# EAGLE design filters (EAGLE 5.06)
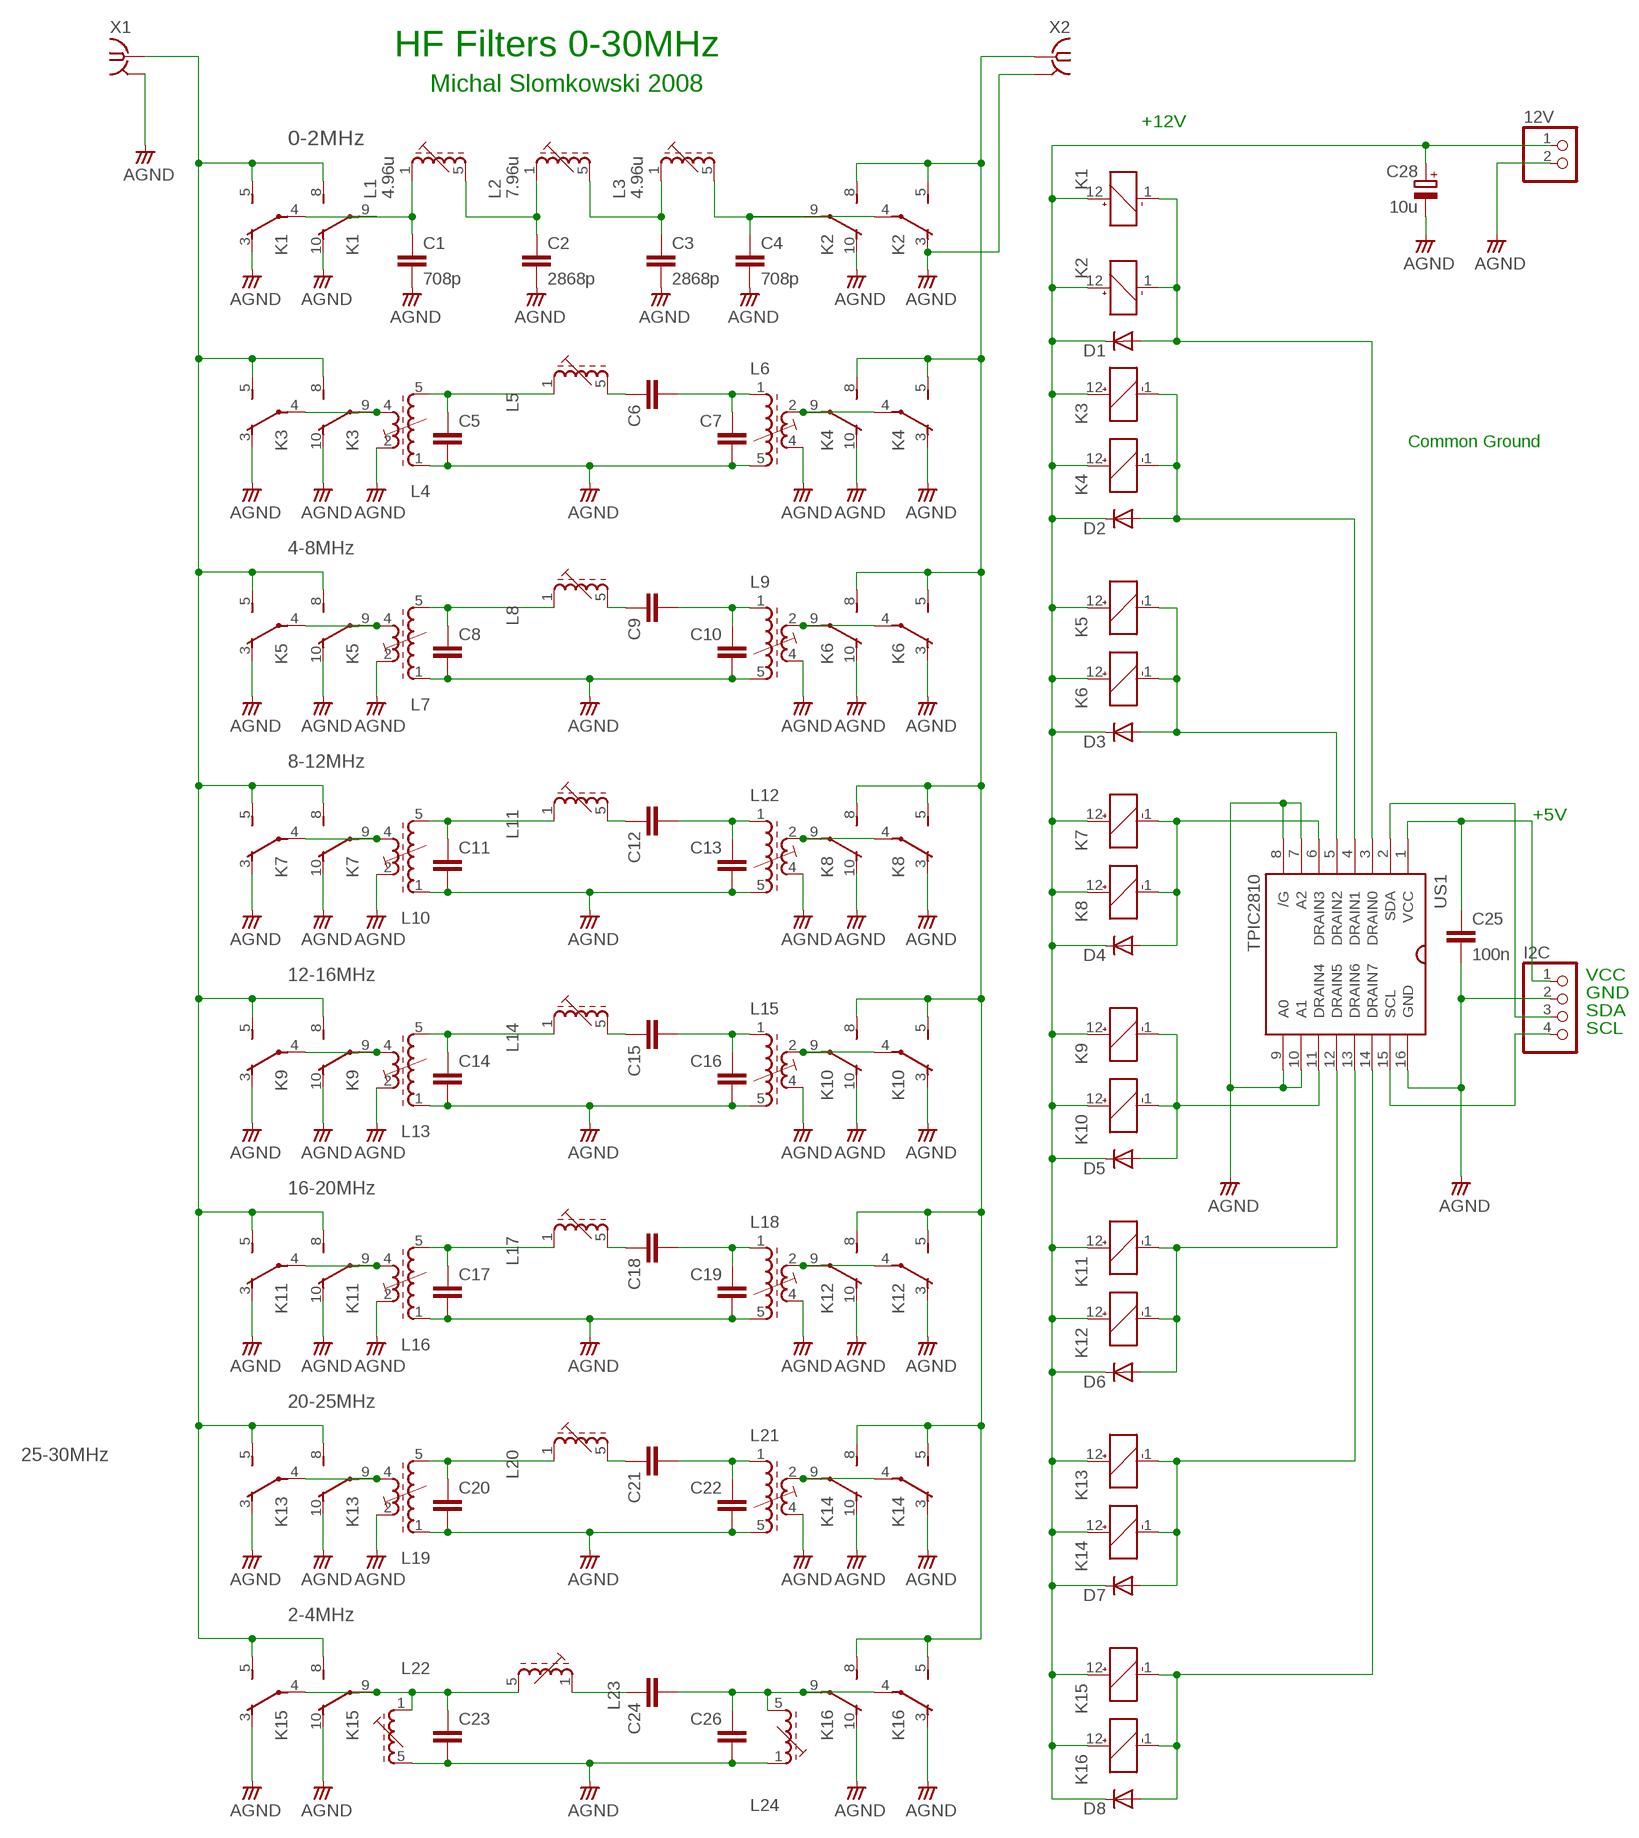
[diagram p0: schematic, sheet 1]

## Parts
12V  PINHD-1X2  [1X02]
C1  708p  C-EU025_050-025X075  [C025_050-025X075]
C2  2868p  C-EU025_050-025X075  [C025_050-025X075]
C3  2868p  C-EU025_050-025X075  [C025_050-025X075]
C4  708p  C-EU025_050-025X075  [C025_050-025X075]
C5  C-EU025_050-025X075  [C025_050-025X075]
C6  C-EU025_050-025X075  [C025_050-025X075]
C7  C-EU025_050-025X075  [C025_050-025X075]
C8  C-EU025_050-025X075  [C025_050-025X075]
C9  C-EU025_050-025X075  [C025_050-025X075]
C10  C-EU025_050-025X075  [C025_050-025X075]
C11  C-EU025_050-025X075  [C025_050-025X075]
C12  C-EU025_050-025X075  [C025_050-025X075]
C13  C-EU025_050-025X075  [C025_050-025X075]
C14  C-EU025_050-025X075  [C025_050-025X075]
C15  C-EU025_050-025X075  [C025_050-025X075]
C16  C-EU025_050-025X075  [C025_050-025X075]
C17  C-EU025_050-025X075  [C025_050-025X075]
C18  C-EU025_050-025X075  [C025_050-025X075]
C19  C-EU025_050-025X075  [C025_050-025X075]
C20  C-EU025_050-025X075  [C025_050-025X075]
C21  C-EU025_050-025X075  [C025_050-025X075]
C22  C-EU025_050-025X075  [C025_050-025X075]
C23  C-EU025_050-025X075  [C025_050-025X075]
C24  C-EU025_050-025X075  [C025_050-025X075]
C25  100n  C-EUC0805K  [C0805K]
C26  C-EU025_050-025X075  [C025_050-025X075]
C28  10u  CPOL-EUE2.5-7  [E2,5-7]
D1  PMLL4150  [SOD80C]
D2  PMLL4150  [SOD80C]
D3  PMLL4150  [SOD80C]
D4  PMLL4150  [SOD80C]
D5  PMLL4150  [SOD80C]
D6  PMLL4150  [SOD80C]
D7  PMLL4150  [SOD80C]
D8  PMLL4150  [SOD80C]
I2C  PINHD-1X4  [1X04]
K1  TX2SO-L-12V  [TX2]
K2  TX2SO-L-12V  [TX2]
K3  TX2SO-L-12V  [TX2]
K4  TX2SO-L-12V  [TX2]
K5  TX2SO-L-12V  [TX2]
K6  TX2SO-L-12V  [TX2]
K7  TX2SO-L-12V  [TX2]
K8  TX2SO-L-12V  [TX2]
K9  TX2SO-L-12V  [TX2]
K10  TX2SO-L-12V  [TX2]
K11  TX2SO-L-12V  [TX2]
K12  TX2SO-L-12V  [TX2]
K13  TX2SO-L-12V  [TX2]
K14  TX2SO-L-12V  [TX2]
K15  TX2SO-L-12V  [TX2]
K16  TX2SO-L-12V  [TX2]
L1  4.96u  51K  [71K]
L2  7.96u  51K  [71K]
L3  4.96u  51K  [71K]
L4  71-4-1524  [71-5]
L5  51K  [71K]
L6  71-4-1524  [71-5]
L7  71-4-1524  [71-5]
L8  51K  [71K]
L9  71-4-1524  [71-5]
L10  71-4-1524  [71-5]
L11  51K  [71K]
L12  71-4-1524  [71-5]
L13  71-4-1524  [71-5]
L14  51K  [71K]
L15  71-4-1524  [71-5]
L16  71-4-1524  [71-5]
L17  51K  [71K]
L18  71-4-1524  [71-5]
L19  71-4-1524  [71-5]
L20  51K  [71K]
L21  71-4-1524  [71-5]
L22  51K  [71K]
L23  51K  [71K]
L24  51K  [71K]
US1  TPIC2810  [SO16]
X1  BU-SMA-V  [BU-SMA-V]
X2  BU-SMA-V  [BU-SMA-V]

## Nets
N$1: C1.1 K1.4(1:P) K1.9(2:P) L1.1(A)
N$2: C2.1 L1.5(E) L2.1(A)
N$3: C3.1 L2.5(E) L3.1(A)
N$4: C5.1 L4.5(E1) L5.1(A)
N$5: K2.5(1:S) K2.8(2:S) K4.5(1:S) K4.8(2:S) K6.5(1:S) K6.8(2:S) K8.5(1:S) K8.8(2:S) K10.5(1:S) K10.8(2:S) K12.5(1:S) K12.8(2:S) K14.5(1:S) K14.8(2:S) K16.5(1:S) K16.8(2:S) X2.1
N$6: K6.4(1:P) K6.9(2:P) L9.2(A2)
N$8: C4.1 K2.4(1:P) K2.9(2:P) L3.5(E)
N$9: D7.A K13.1(_:-) K14.1(_:-) US1.13(DRAIN6)
N$10: K5.4(1:P) K5.9(2:P) L7.4(E2)
N$11: K12.4(1:P) K12.9(2:P) L18.2(A2)
N$12: K4.4(1:P) K4.9(2:P) L6.2(A2)
N$13: C6.2 C7.1 L6.1(A1)
N$14: C6.1 L5.5(E)
N$15: I2C.3 US1.2(SDA)
N$17: K3.4(1:P) K3.9(2:P) L4.4(E2)
N$18: K7.4(1:P) K7.9(2:P) L10.4(E2)
N$19: K13.4(1:P) K13.9(2:P) L19.4(E2)
N$20: C23.1 K15.4(1:P) K15.9(2:P) L22.1(A) L23.5(E)
N$21: C24.1 L23.1(A)
N$22: C24.2 C26.1 K16.4(1:P) K16.9(2:P) L24.5(E)
N$25: K8.4(1:P) K8.9(2:P) L12.2(A2)
N$26: K9.4(1:P) K9.9(2:P) L13.4(E2)
N$27: K1.5(1:S) K1.8(2:S) K3.5(1:S) K3.8(2:S) K5.5(1:S) K5.8(2:S) K7.5(1:S) K7.8(2:S) K9.5(1:S) K9.8(2:S) K11.5(1:S) K11.8(2:S) K13.5(1:S) K13.8(2:S) K15.5(1:S) K15.8(2:S) X1.1
N$28: K10.4(1:P) K10.9(2:P) L15.2(A2)
N$29: C21.2 C22.1 L21.1(A1)
N$30: C21.1 L20.5(E)
N$31: K11.4(1:P) K11.9(2:P) L16.4(E2)
N$32: C20.1 L19.5(E1) L20.1(A)
N$33: C18.2 C19.1 L18.1(A1)
N$34: K14.4(1:P) K14.9(2:P) L21.2(A2)
N$35: C18.1 L17.5(E)
N$36: C17.1 L16.5(E1) L17.1(A)
N$38: C15.2 C16.1 L15.1(A1)
N$39: C15.1 L14.5(E)
N$41: C14.1 L13.5(E1) L14.1(A)
N$42: C12.2 C13.1 L12.1(A1)
N$43: C12.1 L11.5(E)
N$46: D4.A K7.1(_:-) K8.1(_:-) US1.6(DRAIN3)
N$47: D5.A K9.1(_:-) K10.1(_:-) US1.11(DRAIN4)
N$49: C11.1 L10.5(E1) L11.1(A)
N$50: C9.2 C10.1 L9.1(A1)
N$51: C9.1 L8.5(E)
N$52: C8.1 L7.5(E1) L8.1(A)
N$53: D1.A K1.1(_:-) K2.1(_:-) US1.3(DRAIN0)
N$54: D2.A K3.1(_:-) K4.1(_:-) US1.4(DRAIN1)
N$142: D8.A K15.1(_:-) K16.1(_:-) US1.14(DRAIN7)
N$143: D6.A K11.1(_:-) K12.1(_:-) US1.12(DRAIN5)
N$144: D3.A K5.1(_:-) K6.1(_:-) US1.5(DRAIN2)
N$156: C25.1 I2C.1 US1.1(VCC)
N$189: I2C.4 US1.15(SCL)
N$191: 12V.2 C1.2 C2.2 C3.2 C4.2 C5.2 C7.2 C8.2 C10.2 C11.2 C13.2 C14.2 C16.2 C17.2 C19.2 C20.2 C22.2 C23.2 C25.2 C26.2 C28.- I2C.2 K1.3(1:O) K1.10(2:O) K2.3(1:O) K2.10(2:O) K3.3(1:O) K3.10(2:O) K4.3(1:O) K4.10(2:O) K5.3(1:O) K5.10(2:O) K6.3(1:O) K6.10(2:O) K7.3(1:O) K7.10(2:O) K8.3(1:O) K8.10(2:O) K9.3(1:O) K9.10(2:O) K10.3(1:O) K10.10(2:O) K11.3(1:O) K11.10(2:O) K12.3(1:O) K12.10(2:O) K13.3(1:O) K13.10(2:O) K14.3(1:O) K14.10(2:O) K15.3(1:O) K15.10(2:O) K16.3(1:O) K16.10(2:O) L4.1(A1) L4.2(A2) L6.4(E2) L6.5(E1) L7.1(A1) L7.2(A2) L9.4(E2) L9.5(E1) L10.1(A1) L10.2(A2) L12.4(E2) L12.5(E1) L13.1(A1) L13.2(A2) L15.4(E2) L15.5(E1) L16.1(A1) L16.2(A2) L18.4(E2) L18.5(E1) L19.1(A1) L19.2(A2) L21.4(E2) L21.5(E1) L22.5(E) L24.1(A) US1.7(A2) US1.8(/G) US1.9(A0) US1.10(A1) US1.16(GND) X1.2(GND) X2.2(GND) ; supply symbol labelled AGND
N$195: 12V.1 C28.+ D1.C D2.C D3.C D4.C D5.C D6.C D7.C D8.C K1.12(_:+) K2.12(_:+) K3.12(_:+) K4.12(_:+) K5.12(_:+) K6.12(_:+) K7.12(_:+) K8.12(_:+) K9.12(_:+) K10.12(_:+) K11.12(_:+) K12.12(_:+) K13.12(_:+) K14.12(_:+) K15.12(_:+) K16.12(_:+)
Unconnected: L1.S1(S2) L1.S2(S1) L2.S1(S2) L2.S2(S1) L3.S1(S2) L3.S2(S1) L4.S1 L4.S2 L5.S1(S2) L5.S2(S1) L6.S1 L6.S2 L7.S1 L7.S2 L8.S1(S2) L8.S2(S1) L9.S1 L9.S2 L10.S1 L10.S2 L11.S1(S2) L11.S2(S1) L12.S1 L12.S2 L13.S1 L13.S2 L14.S1(S2) L14.S2(S1) L15.S1 L15.S2 L16.S1 L16.S2 L17.S1(S2) L17.S2(S1) L18.S1 L18.S2 L19.S1 L19.S2 L20.S1(S2) L20.S2(S1) L21.S1 L21.S2 L22.S1(S2) L22.S2(S1) L23.S1(S2) L23.S2(S1) L24.S1(S2) L24.S2(S1)

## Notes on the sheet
- HF Filters 0-30MHz
- Michal Slomkowski 2008
- +12V
- 0-2MHz
- Common Ground
- 4-8MHz
- 8-12MHz
- +5V
- 12-16MHz | VCC
- GND
- SDA
- SCL
- 16-20MHz
- 20-25MHz
- 25-30MHz
- 2-4MHz

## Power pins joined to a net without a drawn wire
GND: X1.3(GND) X1.4(GND) X1.5(GND) X2.3(GND) X2.4(GND) X2.5(GND)

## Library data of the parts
12V = pinhead:PINHD-1X2: PIN HEADER
C1-C26 = rcl:C-EU: CAPACITOR, European symbol
C28 = rcl:CPOL-EU: POLARIZED CAPACITOR, European symbol
D1-D8 = diode:PMLL4150: DIODE
I2C = pinhead:PINHD-1X4: PIN HEADER
K1-K16 = relay:TX2SO?-*: 2 AMP. HIGH CAPACITY RELAY NAiS WITH HIGH SURGE VOLTAGE & HIGH BREAKDOWN VOLTAGE Source: http://www.mew-europe.com/.. en_ds_61022_0001.pdf
L1-L3 L5 L8 L11 L14 L17 L20 L22-L24 = inductor-neosid:51K: FILTER pre-adjusted RF filter, type K, standard value E-12
L4 L6 L7 L9 L10 L12 L13 L15 L16 L18 L19 L21 = inductor-neosid:71-4-: TRANSFORMER adjustable filter transformer
US1 = receiver:TPIC2810: 8-Bit LED Driver with I2C Interface
X1 X2 = con-coax:BU-SMA-V: FEMALE SMA CONNECTOR Radiall distributor RS 112-3794

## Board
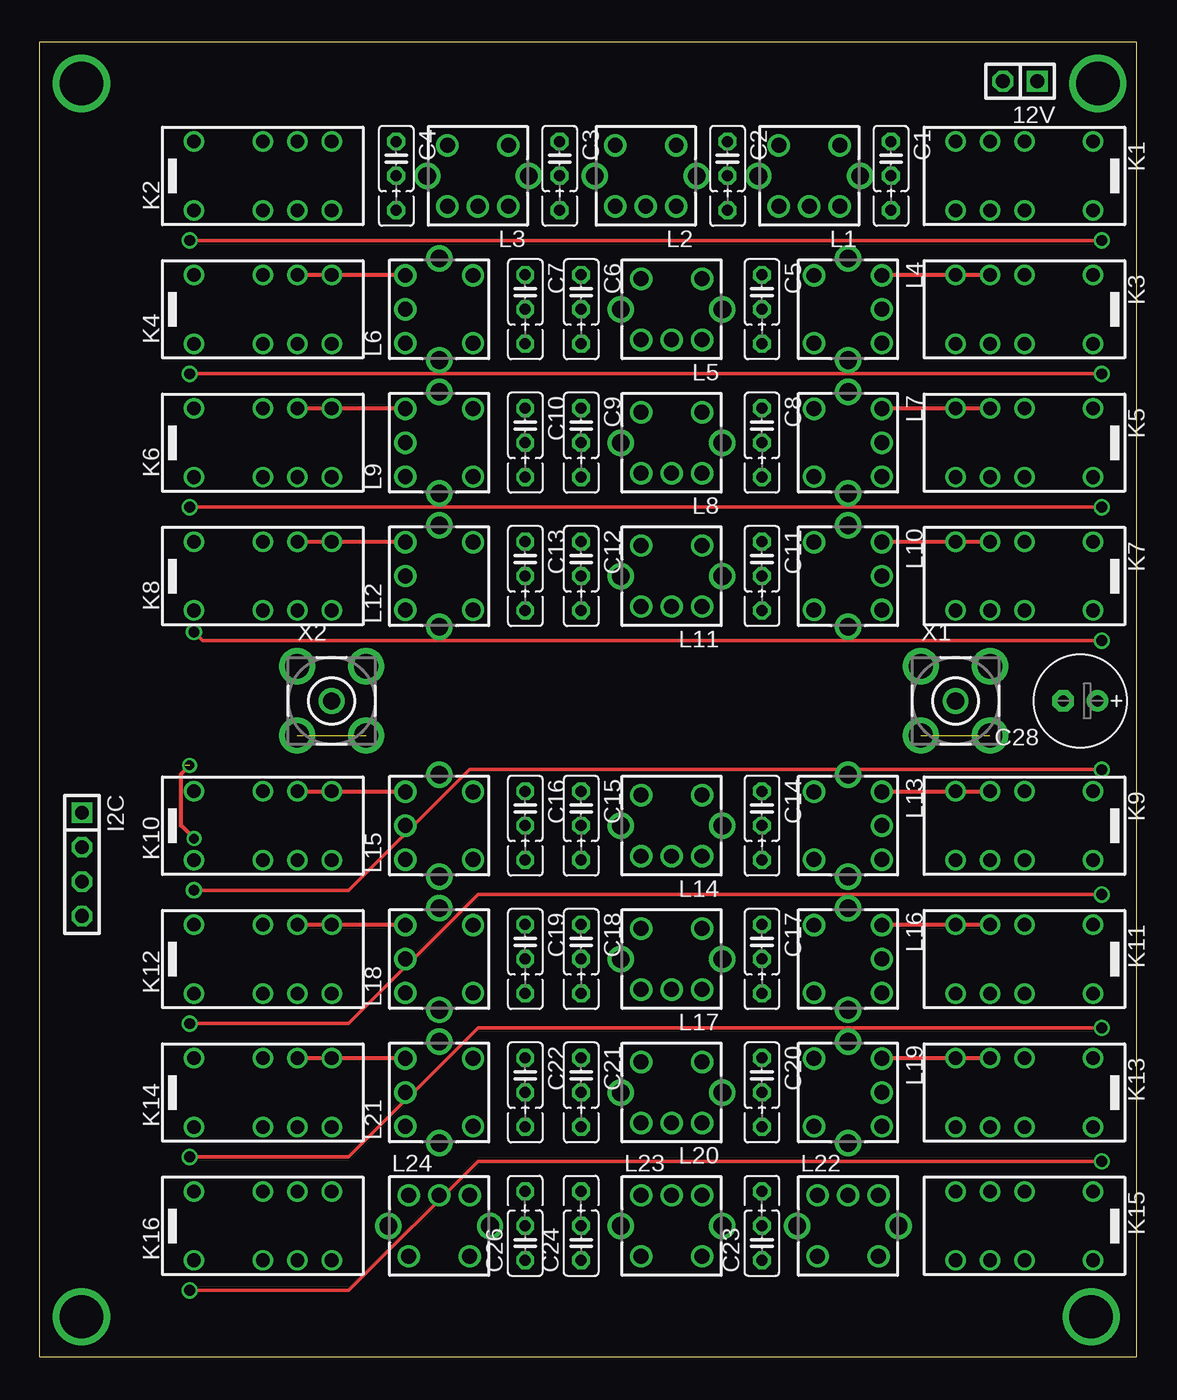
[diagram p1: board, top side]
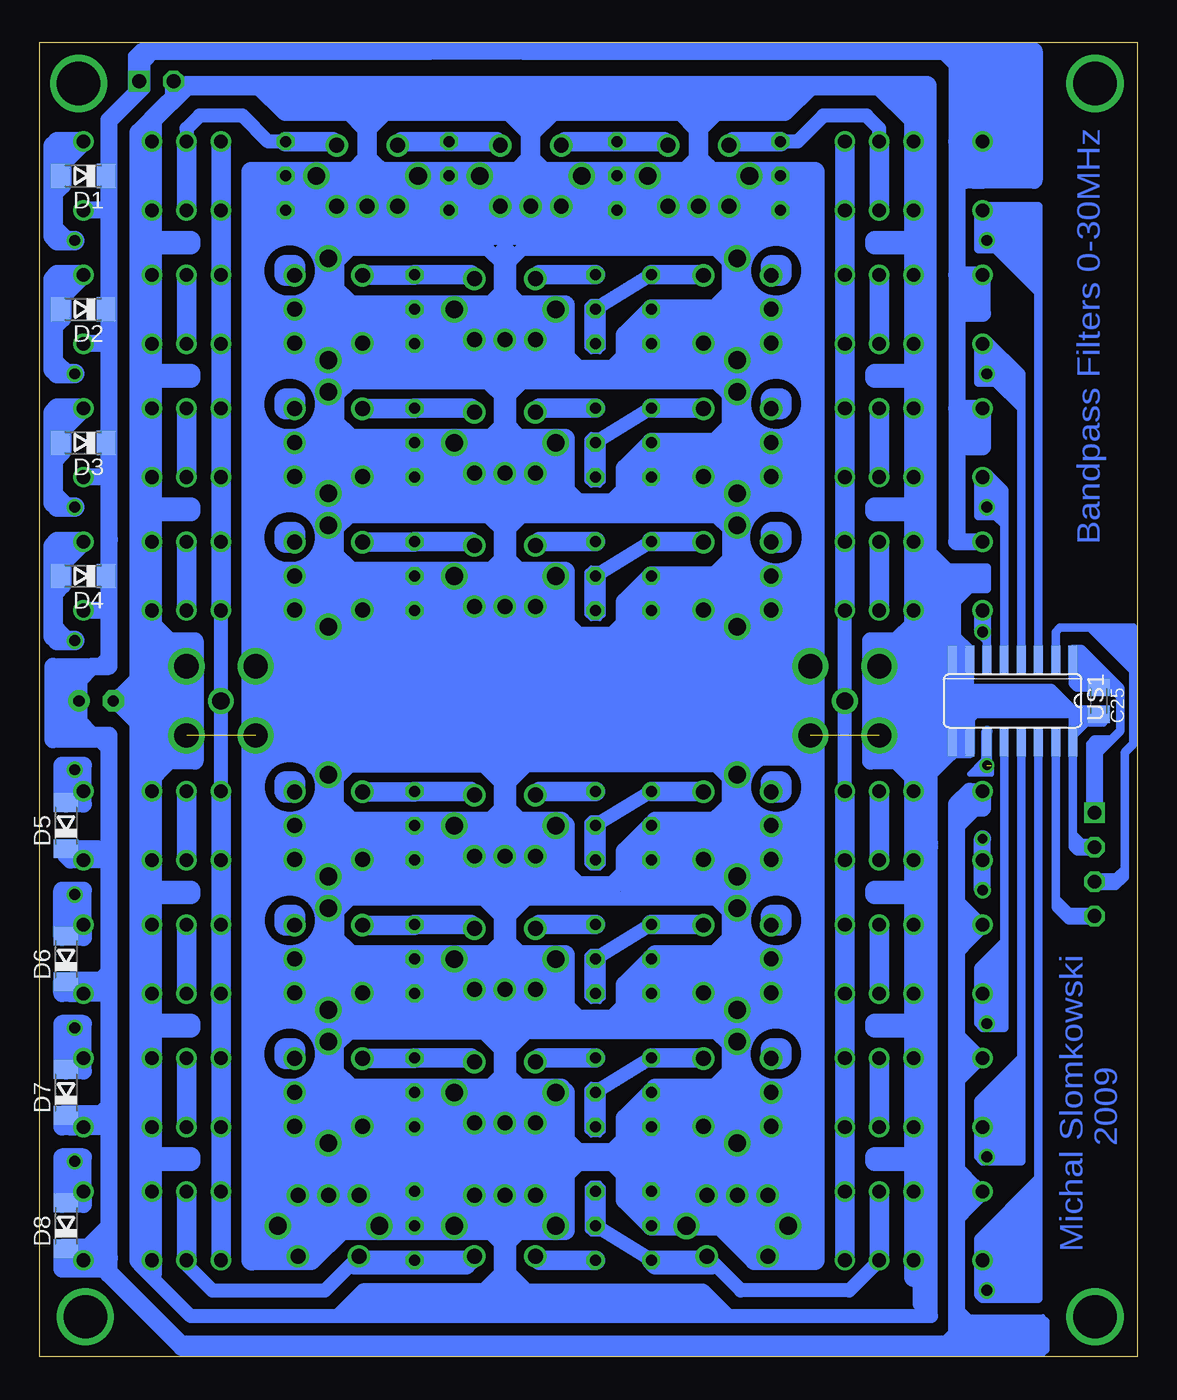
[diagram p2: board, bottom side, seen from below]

Size 81 x 97 mm. Coordinates in mm from the lower left corner, seen from the top.
Outline: 0,0 81,0 81,97 0,97 0,0
Copper layers (1*16): Top 0.035mm / dielectric 1.5mm / Bottom 0.035mm
Design rules "default": minimum track width 10mil, minimum drill 24mil, track to track 8mil, track to pad 8mil, pad to pad 8mil, via to via 8mil, smd to smd 8mil, copper to edge 40mil, drill to drill 8mil, minimum pad ring 10mil, minimum via ring 8mil, stop-mask expansion 4mil, vias tented up to drill 0mil, thermal gap 10mil

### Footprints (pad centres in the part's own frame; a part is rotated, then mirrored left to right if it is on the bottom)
1X02 = drill 1.016 square: 1 -1.27,0 | drill 1.016 octagon: 2 1.27,0
C025_050-025X075 = drill 0.813 octagon: 1 -1.27,0; 2 1.27,0; 3 3.81,0
C0805K = smd 1.3 x 1.6: 1 -1,0; 2 1,0
E2,5-7 = drill 0.813 pad 1.6 round: + -1.27,0 | drill 0.813 pad 1.6 octagon: - 1.27,0
SOD80C = smd 1.4 x 1.8: A 1.7,0; C -1.7,0
1X04 = drill 1.016 square: 1 -3.81,0 | drill 1.016 octagon: 2 -1.27,0; 3 1.27,0; 4 3.81,0
TX2 = drill 1 round: 1 -5.08,-2.54; 3 0,-2.54; 4 2.54,-2.54; 5 5.08,-2.54; 8 5.08,2.54; 9 2.54,2.54; 10 0,2.54; 12 -5.08,2.54
71K = drill 1.1 round: 1 -2.25,-2.25; 2 -2.25,2.25; 3 0,2.25; 4 2.25,2.25; 5 2.25,-2.25 | drill 1.3 round: S1 -3.75,0; S2 3.75,0
71-5 = drill 1.1 round: 1 2.5,-2.5; 2 2.5,2.5; 3 0,2.5; 4 -2.5,2.5; 5 -2.5,-2.5 | drill 1.3 round: S1 -3.75,0; S2 3.75,0
SO16 = smd 0.66 x 2.032: 1 -4.445,-3.073; 2 -3.175,-3.073; 3 -1.905,-3.073; 4 -0.635,-3.073; 5 0.635,-3.073; 6 1.905,-3.073; 7 3.175,-3.073; 8 4.445,-3.073; 9 4.445,3.073; 10 3.175,3.073; 11 1.905,3.073; 12 0.635,3.073; 13 -0.635,3.073; 14 -1.905,3.073; 15 -3.175,3.073; 16 -4.445,3.073
BU-SMA-V = drill 1.27 round: 1 0,0 | drill 1.778 round: 2 -2.55,2.55; 3 2.55,2.55; 4 2.55,-2.55; 5 -2.55,-2.55

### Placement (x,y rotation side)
12V  72.38,94.13 180 top
C1  62.86,88.42 270 top
C2  50.8,88.42 270 top
C3  38.41,88.42 270 top
C4  26.35,88.42 270 top
C5  53.34,78.58 270 top
C6  40,78.58 270 top
C7  35.87,78.58 270 top
C8  53.34,68.73 270 top
C9  40,68.73 270 top
C10  35.87,68.73 270 top
C11  53.34,58.89 270 top
C12  40,58.89 270 top
C13  35.87,58.89 270 top
C14  53.34,40.48 270 top
C15  40,40.48 270 top
C16  35.87,40.48 270 top
C17  53.34,30.63 270 top
C18  40,30.63 270 top
C19  35.87,30.63 270 top
C20  53.34,20.79 270 top
C21  40,20.79 270 top
C22  35.87,20.79 270 top
C23  53.34,8.41 90 top
C24  40,8.41 90 top
C25  2.85,48.41 270 bottom
C26  35.87,8.41 90 top
C28  76.83,48.41 180 top
D1  77.78,87.15 180 bottom
D2  77.78,77.3 180 bottom
D3  77.78,67.46 180 bottom
D4  77.78,57.62 180 bottom
D5  79.05,39.2 90 bottom
D6  79.05,29.36 90 bottom
D7  79.05,19.52 90 bottom
D8  79.05,9.68 90 bottom
I2C  3.17,36.35 270 top
K1  72.7,87.15 180 top
K2  16.5,87.15 0 top
K3  72.7,77.3 180 top
K4  16.5,77.3 0 top
K5  72.7,67.46 180 top
K6  16.5,67.46 0 top
K7  72.7,57.62 180 top
K8  16.5,57.62 0 top
K9  72.7,39.2 180 top
K10  16.5,39.2 0 top
K11  72.7,29.36 180 top
K12  16.5,29.36 0 top
K13  72.7,19.52 180 top
K14  16.5,19.52 0 top
K15  72.7,9.68 180 top
K16  16.5,9.68 0 top
L1  56.83,87.15 180 top
L2  44.76,87.15 180 top
L3  32.38,87.15 180 top
L4  59.69,77.3 270 top
L5  46.67,77.3 180 top
L6  29.52,77.3 90 top
L7  59.69,67.46 270 top
L8  46.67,67.46 180 top
L9  29.52,67.46 90 top
L10  59.69,57.62 270 top
L11  46.67,57.62 180 top
L12  29.52,57.62 90 top
L13  59.69,39.2 270 top
L14  46.67,39.2 180 top
L15  29.52,39.2 90 top
L16  59.69,29.36 270 top
L17  46.67,29.36 180 top
L18  29.52,29.36 90 top
L19  59.69,19.52 270 top
L20  46.67,19.52 180 top
L21  29.52,19.52 90 top
L22  59.69,9.68 0 top
L23  46.67,9.68 0 top
L24  29.52,9.68 0 top
US1  9.2,48.41 180 bottom
X1  67.62,48.41 0 top
X2  21.58,48.41 0 top

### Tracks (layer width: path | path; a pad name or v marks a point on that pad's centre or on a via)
GND  (2 unrouted)
  Bottom 0.61: 65.08,45.87 X1.5 X2.4 24.12,45.87 24.13,45.88 X2.3 | X1.4 70.16,45.87 70.17,45.88 X1.3
N$1
  Bottom 1.016: K1.4 70.16,90.64 69.21,91.59 66.03,91.59 64.13,89.69 C1.1
  Bottom 1.422: 59.05,89.37 L1.1 59.37,89.69 C1.1 | K1.4 K1.9
N$2
  Bottom 1.422: 46.98,89.37 L2.1 47.3,89.69 C2.1 54.29,89.69 L1.5 54.61,89.37
N$3
  Bottom 1.422: 34.6,89.37 L3.1 34.92,89.69 C3.1 42.22,89.69 L2.5 42.54,89.37
N$4
  Bottom 1.422: L4.5 53.38,79.8 C5.1 49.21,79.84 L5.1 48.89,79.53
N$5
  Bottom 1.016: K8.5 X2.1 K10.8
  Bottom 1.422: K10.8 K10.5 K12.8 K12.5 | K12.5 21.58,26.5 | K12.5 K14.8 K14.5 K16.8 K16.5 | K8.5 K8.8 K6.5 K6.8 K4.5 K4.8 K2.5 K2.8
N$6
  Top 0.305: L9.2 26.98,70 K6.9
  Bottom 1.422: K6.4 K6.9
N$7
  Bottom 0.305: 70.48,0.15 6.98,0.15 6.66,0.47 6.66,2.69 6.98,3.01 12.38,3.01 12.7,3.33 | 12.7,3.33 13.01,3.64 | 12.7,2.69 12.7,3.33
  Bottom 0.61: 6.98,2.69 12.7,2.69
N$8
  Bottom 1.016: K2.9 19.04,90.64 20,91.59 23.17,91.59 25.08,89.69 C4.1
  Bottom 1.422: 30.16,89.37 L3.5 29.84,89.69 C4.1 | K2.4 K2.9
N$9  (via drill 0.8)
  Top 0.254: v78.42,24.28 32.38,24.28 22.86,14.76 v11.11,14.76
  Bottom 0.61: 8.57,20.15 8.57,19.84 K14.1 11.11,16.98 11.11,15.08 v11.11,14.76 | 8.57,20.15 8.57,22.06 | 8.57,22.06 US1.13 | 8.57,20.15 8.57,14.44 11.43,14.44 11.74,14.76 11.74,18.88 8.57,22.06
  Bottom 1.27: 11.11,15.08 11.11,18.57
  Bottom 1.422: D7.A 79.05,21.42 78.42,22.06 K13.1 78.42,22.7 v78.42,24.28
N$10
  Top 0.305: L7.4 62.23,70 K5.4
  Bottom 1.422: K5.4 K5.9
N$11
  Top 0.305: L18.2 26.98,31.9 K12.9
  Bottom 1.422: K12.4 K12.9
N$12
  Top 0.305: L6.2 26.98,79.84 K4.9
  Bottom 1.422: K4.4 K4.9
N$13
  Bottom 1.016: C7.1 C6.2
  Bottom 1.422: L6.1 32.06,79.84 C7.1
N$14
  Bottom 1.422: 44.45,79.53 L5.5 44.13,79.84 C6.1
N$15
  Bottom 0.61: US1.2 6.03,53.49 5.71,53.81 3.49,53.81 | 3.49,53.81 0.31,50.63 0.31,50.32 | 0.31,50.32 0.31,45.24 0.95,44.6 0.95,36.03 | 0.95,35.71 0.95,36.03 | 0.95,35.71 1.58,35.08 I2C.3 | 0.31,50.32 0.31,53.81 3.49,53.81 | 0.95,36.03 1.58,35.39 3.17,35.39 3.49,35.08 3.17,34.76 1.58,34.76 0.95,35.39 0.95,35.71
N$16
  Bottom 1.27: 15.55,45.55 15.55,43.65
N$17
  Top 0.305: L4.4 62.23,79.84 K3.4
  Bottom 1.422: K3.4 K3.9
N$18
  Top 0.305: L10.4 62.23,60.16 K7.4
  Bottom 1.422: K7.4 K7.9
N$19
  Top 0.305: L19.4 62.23,22.06 K13.4
  Bottom 1.422: K13.4 K13.9
N$20
  Bottom 1.016: K15.9 70.16,6.82 68.26,4.92 59.95,4.92 L22.1
  Bottom 1.422: K15.9 K15.4 | L22.1 57.15,7.14 C23.1 49.21,7.14 L23.5
N$21
  Bottom 1.422: C24.1 44.13,7.14 L23.1
N$22
  Bottom 1.016: C24.2 C26.1 32.06,7.14 L24.5 29.26,4.92 21.27,4.92 K16.4
  Bottom 1.422: K16.4 K16.9 | 31.74,7.14 C26.1 35.55,6.82 31.43,6.82
N$23
  Bottom 1.422: 48.89,7.46 49.53,6.82 57.78,6.82
N$24
  Bottom 0.305: 40.64,9.36 40.32,9.04 39.37,9.04 39.37,12.54 39.68,12.85 40.32,12.85 40.64,12.54 40.64,9.36
N$25
  Top 0.305: L12.2 26.98,60.16 K8.9
  Bottom 1.422: K8.4 K8.9
N$26
  Top 0.305: L13.4 62.23,41.74 K9.4
  Bottom 1.422: K9.4 K9.9
N$27
  Bottom 1.016: K9.5 X1.1 K7.8
  Bottom 1.422: K15.8 K15.5 K13.8 K13.5 K11.8 K11.5 K9.8 K9.5 | K7.8 K7.5 K5.8 K5.5 K3.8 K3.5 K1.8 K1.5
N$28
  Top 0.305: L15.2 26.98,41.74 K10.9
  Bottom 1.422: K10.4 K10.9
N$29
  Bottom 1.016: C22.1 C21.2
  Bottom 1.422: L21.1 32.06,22.06 C22.1
N$30
  Bottom 1.422: 44.45,21.74 L20.5 44.13,22.06 C21.1
N$31
  Top 0.305: L16.4 62.23,31.9 K11.4
  Bottom 1.422: K11.4 K11.9
N$32
  Bottom 1.422: L19.5 53.38,22.02 C20.1 49.21,22.06 L20.1 48.89,21.74
N$33
  Bottom 1.016: C19.1 C18.2
  Bottom 1.422: L18.1 32.06,31.9 C19.1
N$34
  Top 0.305: L21.2 26.98,22.06 K14.9
  Bottom 1.422: K14.4 K14.9
N$35
  Bottom 1.422: 44.45,31.58 L17.5 44.13,31.9 C18.1
N$36
  Bottom 1.422: L16.5 53.38,31.86 C17.1 49.21,31.9 L17.1 48.89,31.58
N$37
  Bottom 1.016: 7.62,79.84 10.47,82.7
N$38
  Bottom 1.016: C16.1 C15.2
  Bottom 1.422: L15.1 32.06,41.74 C16.1
N$39
  Bottom 1.422: 44.45,41.43 L14.5 44.13,41.74 C15.1
N$40  (via drill 3.2)
  other vias: 3.13,2.97
N$41
  Bottom 1.422: L13.5 53.38,41.7 C14.1 49.21,41.74 L14.1 48.89,41.43
N$42
  Bottom 1.016: C13.1 C12.2
  Bottom 1.422: L12.1 32.06,60.16 C13.1
N$43
  Bottom 1.422: 44.45,59.84 L11.5 44.13,60.16 C12.1
N$44
  Bottom 0.305: 39.68,12.54 40.32,12.54
N$45
  Bottom 1.016: 10.47,73.18 10.16,73.18 8.89,71.91 8.89,70.95 10.47,72.54
N$46  (via drill 0.8)
  Top 0.254: v78.42,52.86 12.06,52.86 v11.43,53.49
  Bottom 0.61: US1.6 11.11,52.86 | 11.11,52.86 11.11,54.76 K8.1 | 11.74,55.4 11.74,53.49 11.11,52.86
  Bottom 1.016: K8.1 v11.43,53.49
  Bottom 1.422: v78.42,52.86 79.69,52.86 80,53.17 80,54.13 | 80,54.13 80,57.62 | 80,57.62 80,59.84 79.69,60.16 K7.1 79.37,58.57 79.37,56.98 79.69,56.67 | 80,57.62 D4.A | 80,54.13 80,53.81 79.37,53.17
N$47  (via drill 0.7, 0.8)  (1 unrouted)
  Top 0.254: v78.42,43.33 31.74,43.33 22.86,34.44 v11.43,34.44
  Top 0.305: v11.11,43.65 10.47,43.02 10.47,39.2 v11.43,38.25
  Bottom 0.406: 10.79,43.33 10.79,43.65 | 10.79,43.33 10.79,43.02 12.38,43.02 11.43,43.97 | 11.43,43.33 11.74,43.33 | 11.43,43.33 10.79,43.33 | 11.43,43.33 11.43,43.65
  Bottom 0.61: v11.11,43.65 US1.11
  Bottom 0.813: v11.11,43.65 11.11,46.19
  Bottom 1.27: v11.43,38.25 K10.1 v11.43,34.44
  Bottom 1.422: v78.42,43.33 78.42,42.38 K9.1 78.42,41.74 79.05,41.11 D5.A
N$48
  Bottom 1.016: 10.47,62.38 10.47,63.34
N$49
  Bottom 1.422: L10.5 53.38,60.12 C11.1 49.21,60.16 L11.1 48.89,59.84
N$50
  Bottom 1.016: C10.1 C9.2
  Bottom 1.422: L9.1 32.06,70 C10.1
N$51
  Bottom 1.422: 44.45,69.69 L8.5 44.13,70 C9.1
N$52
  Bottom 1.422: L7.5 53.38,69.96 C8.1 49.21,70 L8.1 48.89,69.69
N$53  (via drill 0.8)
  Top 0.254: v11.11,82.39 v78.42,82.39
  Bottom 0.61: US1.3 7.3,78.58 | 7.3,78.58 7.3,80.16 | 7.3,80.16 7.3,80.48 K2.1 | 7.3,80.16 7.3,84.92 11.43,84.92 11.74,84.61 11.74,81.75 10.47,81.75 7.3,78.58
  Bottom 1.422: v78.42,82.39 79.05,82.39 | 79.05,82.39 79.69,82.39 80,82.7 80,83.66 | K2.1 11.11,83.97 v11.11,82.39 | 80,83.66 80,85.88 | 80,85.88 80,87.15 | 80,87.15 80,89.37 79.69,89.69 K1.1 79.37,88.1 79.37,86.51 80,85.88 | 80,87.15 D1.A | 80,83.66 80,83.34 79.05,82.39
N$54  (via drill 0.8)
  Top 0.254: v11.11,72.54 v78.42,72.54
  Bottom 0.61: US1.4 8.57,70 | 8.57,70 8.57,71.59 | 8.57,71.59 8.57,71.91 K4.1 | 8.57,71.59 8.57,72.54 11.11,75.08 11.74,74.45 11.74,71.91 10.47,71.91 8.57,70
  Bottom 1.422: v11.11,72.54 11.11,74.45 K4.1 | v78.42,72.54 79.69,72.54 80,72.86 80,73.81 | 80,73.81 80,76.03 | 80,76.03 80,77.3 | 80,77.3 80,79.53 79.69,79.84 K3.1 79.37,78.26 79.37,76.67 80,76.03 | 80,77.3 D2.A | 80,73.81 80,73.5 79.37,72.86
N$55
  Bottom 1.27: 12.7,40.48 11.74,41.43
N$56  (via drill 3.2)
  other vias: 77.63,2.97
N$57  (via drill 3.2)
  other vias: 78.13,93.97
N$58  (via drill 3.2)
  other vias: 3.13,93.97
N$59
  Bottom 1.676: 62.23,79.84 62.86,79.84 62.86,80.48 62.23,80.48 62.23,80.16
N$60
  Bottom 1.676: 26.98,79.84 26.98,80.48 26.35,80.48 26.35,79.84 26.66,79.84
N$61
  Bottom 1.676: 62.23,70 62.86,70 62.86,70.64 62.23,70.64 62.23,70.32
N$62
  Bottom 1.676: 62.23,60.16 62.86,60.16 62.86,60.8 62.23,60.8 62.23,60.16
N$63
  Bottom 1.676: 26.98,70 26.98,70.64 26.35,70.64 26.35,70 26.98,70
N$64
  Bottom 1.676: 26.98,60.16 26.98,60.8 26.35,60.8 26.35,60.16 26.98,60.16
N$65
  Bottom 1.676: 26.98,41.74 26.98,42.38 26.35,42.38 26.35,41.74 26.98,41.74
N$66
  Bottom 1.676: 26.98,31.9 26.98,32.54 26.35,32.54 26.35,31.9 26.98,31.9
N$67
  Bottom 1.676: 26.98,22.06 26.98,22.7 26.35,22.7 26.35,22.06 26.98,22.06
N$69
  Bottom 1.676: 62.23,41.74 62.23,42.38 62.86,42.38 62.86,41.74 62.54,41.74
N$70
  Bottom 1.676: 62.23,31.9 62.23,32.54 62.86,32.54 62.86,31.9 62.54,31.9
N$71
  Bottom 1.676: 62.23,22.06 62.23,22.7 62.86,22.7 62.86,22.06 62.23,22.06
N$73
  Bottom 1.016: 64.77,78.89 64.77,78.58 64.45,78.26
N$74
  Bottom 1.016: 73.66,6.82 69.84,3.01 59.05,3.01 | 30.16,3.01 15.24,3.01 15.24,37.62 | 30.16,3.01 59.05,3.01 | 15.24,37.62 15.24,37.94 | 15.24,37.62 15.24,43.33 | 47.62,4.92 46.67,4.92 45.72,4.92 | 47.62,4.92 48.26,4.92 | 48.26,4.92 57.15,4.92 59.05,3.01 | 45.72,4.92 45.08,4.92 | 45.08,4.92 32.06,4.92 30.16,3.01 | 46.67,5.87 45.72,4.92 | 46.98,5.87 46.98,5.55 47.62,4.92 | 46.67,6.5 45.08,4.92 | 46.67,6.18 46.98,6.18 48.26,4.92
  Bottom 1.676: 46.67,3.64 46.67,4.92 46.67,5.87 46.67,6.18 46.67,6.5 46.67,43.02
N$75
  Bottom 1.676: 46.67,58.25 46.67,81.43
N$76
  Bottom 1.016: 63.81,68.1 64.77,69.05
N$77
  Bottom 1.016: 24.44,78.89 24.44,78.58 25.08,77.94
N$78
  Bottom 1.016: 24.44,68.73 24.44,68.41 24.76,68.1
N$79
  Bottom 1.016: 24.44,58.89 24.44,58.57 25.08,57.94
N$80
  Bottom 1.676: 47.62,72.54 47.62,72.22 47.3,71.91
N$81
  Bottom 1.422: 72.38,62.7 69.84,62.7 69.84,62.38 72.38,62.38
N$82
  Bottom 1.016: 24.76,10.31 24.44,10.63
N$83
  Bottom 1.016: 24.44,21.11 24.44,20.79 24.76,20.47
N$84
  Bottom 1.016: 24.44,30.63 24.44,30.31 24.76,30
N$85
  Bottom 1.016: 64.77,30.95 64.77,30.31 64.45,30
N$86
  Bottom 1.016: 64.45,20.47 64.77,20.79
N$87
  Bottom 1.016: 64.77,10.95 64.45,10.95
N$88
  Bottom 1.676: 64.13,72.54 64.77,71.91
N$89
  Bottom 1.676: 60.64,72.54 60.64,72.22 59.69,71.27 | 59.69,71.27 59.69,71.91 59.05,72.54 | 59.69,71.27 59.69,69.05 60,68.73
N$90
  Bottom 1.676: 64.45,82.7 64.77,82.39
N$91
  Bottom 1.676: 60.64,82.39 59.37,82.39 59.05,82.07 59.69,81.43 59.69,78.89 60,78.58
N$92
  Bottom 1.676: 24.76,82.39 24.76,82.07 24.44,81.75
N$93
  Bottom 1.676: 28.57,82.7 29.52,81.75 29.84,81.75 30.16,82.07
N$94
  Bottom 1.676: 29.52,81.43 29.52,78.89 28.57,77.94
N$95
  Bottom 1.676: 24.76,72.22 24.44,72.22
N$96
  Bottom 1.676: 37.14,73.18 37.78,72.54
N$97
  Bottom 1.676: 28.57,72.54 28.89,72.54 29.52,71.91 30.47,71.91
N$98
  Bottom 1.676: 29.52,71.59 29.52,68.73 28.89,68.1
N$99
  Bottom 1.676: 64.45,62.7 64.77,62.38
N$100
  Bottom 1.676: 64.77,58.57 65.08,58.89
N$101
  Bottom 1.676: 60.32,62.7 60.32,62.06 59.69,61.43 59.69,61.75 59.05,62.38
N$102
  Bottom 1.676: 59.69,60.8 59.69,58.89 60,58.57
N$103
  Bottom 1.422: 37.46,63.34 37.46,63.02 37.78,62.7
N$104
  Bottom 1.422: 24.76,62.7 24.44,62.38
N$105
  Bottom 1.422: 28.89,62.7 28.89,62.38 29.2,62.06 30.47,62.06
N$106
  Bottom 1.422: 29.52,61.43 29.52,58.89 28.89,58.25
N$107
  Bottom 0.305: 39.05,57.94 39.37,57.62 39.37,54.76 39.68,54.45 40.32,54.45 40.64,54.76 40.64,57.94 40.32,58.25 39.37,58.25
N$108
  Bottom 0.305: 39.37,68.1 40.32,68.1 40.64,67.78 40.64,64.61 40.32,64.29 39.68,64.29 39.37,64.61 39.37,67.78
N$109
  Bottom 0.305: 39.68,77.94 40.32,77.94 40.64,77.62 40.64,74.45 40.32,74.13 39.68,74.13 39.37,74.45 39.37,77.62
N$110
  Bottom 0.305: 39.68,39.84 40.32,39.84 40.64,39.52 40.64,36.35 40.32,36.03 39.68,36.03 39.37,36.35 39.37,39.52
N$111
  Bottom 0.305: 39.68,30 40.32,30 40.64,29.68 40.64,26.5 40.32,26.19 39.68,26.19 39.37,26.5 39.37,29.68
N$112
  Bottom 0.305: 39.68,20.15 40.32,20.15 40.64,19.84 40.64,16.66 40.32,16.34 39.68,16.34 39.37,16.66 39.37,19.52
N$114
  Bottom 0.406: 40.32,36.35 39.68,36.35
N$115
  Bottom 0.406: 40.32,26.5 39.68,26.5
N$116
  Bottom 1.422: 31.74,3.96 57.46,3.96
N$117
  Bottom 0.406: 40.32,16.66 39.68,16.66
N$118
  Bottom 1.27: 30.47,34.44 30.47,33.81 29.52,32.85
  Bottom 1.422: 28.89,34.12 29.52,33.49 29.52,32.85 29.52,30.95 28.89,30.31
N$119
  Bottom 1.422: 25.08,34.76 25.08,34.44 24.44,33.81
N$120
  Bottom 1.422: 24.44,23.96 25.08,24.6
N$121
  Bottom 1.422: 24.76,15.08 24.76,14.44 24.44,14.12
N$122
  Bottom 1.422: 30.47,14.76 30.47,14.44 29.2,14.44
N$124
  Bottom 1.422: 45.72,14.12 45.72,14.44
N$125
  Bottom 1.422: 48.26,14.76 48.26,14.44 47.62,13.81
N$126
  Bottom 1.422: 64.45,14.76 64.45,14.44 64.77,14.12
N$127
  Bottom 1.422: 60.64,14.76 60.64,14.44 60,13.81 59.69,13.81 58.73,14.76
N$129
  Bottom 1.422: 64.45,24.6 64.45,24.28 64.77,23.96
N$130
  Bottom 1.422: 60.64,24.92 60.64,24.28 59.69,23.33 59.69,23.96 59.05,24.6
N$131
  Bottom 1.422: 59.69,23.01 59.69,21.11 60,20.79
N$132
  Bottom 1.422: 47.3,23.96 47.62,24.28
N$133
  Bottom 1.422: 30.47,24.28 30.16,24.28 29.52,23.65 29.52,23.96 28.89,24.6
N$134
  Bottom 1.422: 29.52,23.01 29.52,21.11 29.2,20.79
N$135
  Bottom 1.422: 36.83,27.14 36.83,25.23 37.46,24.6
N$136
  Bottom 1.422: 64.45,34.12 64.45,34.44
N$137
  Bottom 1.422: 60.64,34.44 59.69,33.49 59.69,30.95 60.32,30.31
N$138
  Bottom 1.422: 58.41,34.44 58.73,34.12 59.05,34.12 59.37,33.81
N$139
  Bottom 1.422: 47.3,33.81 47.94,34.44
N$140
  Bottom 1.422: 36.83,17.3 36.83,15.39 37.46,14.76
N$141
  Bottom 1.422: 37.14,36.98 37.14,34.44 37.46,34.12
N$142  (via drill 0.8)
  Top 0.254: v78.42,14.44 32.38,14.44 22.86,4.92 v11.11,4.92
  Bottom 0.61: 7.3,11.27 7.3,13.17 | 7.3,13.17 US1.14 | 7.3,11.27 K16.1 11.11,7.14 11.11,5.23 v11.11,4.92 | 7.3,11.27 7.3,4.28 11.43,4.28 11.74,4.6 11.74,8.73 7.3,13.17
  Bottom 1.27: 11.11,5.23 11.11,8.73 | 7.93,4.92 v11.11,4.92 | K15.1 77.78,11.27 79.37,11.27 79.37,14.76 77.78,14.76 K15.1
  Bottom 1.422: D8.A 79.05,11.58 78.42,12.22 K15.1 78.42,12.85 v78.42,14.44
N$143  (via drill 0.8)
  Top 0.254: v78.42,34.12 32.38,34.12 22.86,24.6 v11.11,24.6
  Bottom 0.61: 9.84,28.73 9.84,28.41 11.11,27.14 | 9.84,28.73 9.84,30.63 | 9.84,30.63 US1.12 | 11.11,27.14 K12.1 | 11.11,27.14 11.11,24.92 v11.11,24.6 | 9.84,28.73 9.84,24.28 11.43,24.28 11.74,24.6 11.74,28.73 9.84,30.63
  Bottom 1.27: K11.1 77.78,32.22 | 77.78,32.22 77.78,34.44 79.37,34.44 79.37,30.95 77.78,30.95 77.78,32.22 | 11.11,24.92 11.11,28.73
  Bottom 1.422: D6.A 79.05,31.27 78.42,31.9 K11.1 78.42,32.54 v78.42,34.12
N$144  (via drill 0.8)
  Top 0.254: v11.11,62.7 v78.42,62.7
  Bottom 0.61: 11.74,64.92 11.74,62.06 10.47,62.06 9.84,61.43 | US1.5 9.84,61.43 | 9.84,61.43 9.84,63.02 | 9.84,63.02 9.84,63.34 K6.1 | 9.84,63.02 9.84,63.97 11.11,65.24
  Bottom 1.422: v11.11,62.7 11.11,64.61 K6.1 | v78.42,62.7 79.05,62.7 | 79.05,62.7 79.69,62.7 80,63.02 80,63.65 | 80,63.65 80,66.19 | 80,66.19 80,67.46 | 80,67.46 80,69.69 79.69,70 K5.1 79.37,68.41 79.37,66.83 80,66.19 | 80,67.46 D3.A | 79.05,62.7 80,63.65
N$145
  Bottom 1.27: 10.16,24.92 10.16,29.68
N$146
  Bottom 1.27: 9.2,15.08 9.2,20.79
N$147
  Bottom 1.27: 9.84,15.08 9.84,20.15
N$148
  Bottom 1.27: 11.43,79.53 11.43,76.99 12.7,76.99
N$149
  Bottom 1.422: 25.71,93.18 62.54,93.18
N$150
  Bottom 1.422: 72.38,34.44 69.84,34.44 69.84,34.12 72.38,34.12
N$151
  Bottom 1.27: 12.38,77.94 12.38,79.21
N$152
  Bottom 1.422: 16.82,24.6 19.36,24.6 19.36,24.28 17.14,24.28
N$153
  Bottom 1.422: 16.82,34.44 19.36,34.44 19.36,34.12 16.82,34.12
N$154
  Bottom 1.27: 10.47,15.08 10.47,19.52
N$155
  Bottom 0.61: 2.54,47.78 4.76,47.78 6.34,49.37 12.38,49.37 12.38,52.22 13.33,53.17 13.33,55.71 12.38,56.67 11.11,56.67 11.11,58.25 13.97,58.25 15.24,59.52
N$156
  Bottom 0.61: 4.76,52.22 4.12,52.22 1.27,49.37 1.27,48.73 | 4.76,49.68 4.67,49.59 | 4.76,49.68 US1.1 | 4.76,49.68 4.49,49.41 C25.1 1.95,49.41 1.27,48.73 | 1.27,48.73 1.27,46.19 1.9,45.55 | 1.9,45.55 3.17,45.55 | 3.17,45.55 I2C.1 | 3.17,45.55 3.49,45.24 3.49,39.84 2.85,39.84 2.85,44.6 1.9,45.55 | 1.9,45.55 2.54,45.55 2.85,45.24
N$157
  Bottom 1.27: 7.93,5.23 7.93,11.9
N$159
  Bottom 1.422: 15.87,3.96 15.87,6.18
N$162
  Bottom 1.422: 64.13,44.28 64.45,44.28 65.08,43.65
N$163
  Bottom 1.422: 64.77,40.79 64.77,40.48 64.13,39.84
N$164
  Bottom 1.422: 60.64,44.28 60.64,43.65 59.69,42.7 59.69,40.79 60.32,40.16
N$165
  Bottom 1.422: 58.73,44.28 59.69,43.33
N$166
  Bottom 1.422: 45.72,43.65 47.62,43.65
N$167
  Bottom 1.422: 28.89,40.16 29.2,40.16 29.2,43.02 29.84,43.65 28.89,43.65
N$168
  Bottom 1.422: 24.44,40.48 24.44,40.16
N$169
  Bottom 1.27: 13.01,44.92 13.01,47.14
N$170
  Bottom 1.27: 13.01,49.37 13.01,51.91 13.33,52.22
N$171
  Bottom 1.27: 14.92,58.57 14.6,58.25
N$172
  Bottom 1.27: 11.74,57.62 13.33,57.62 13.33,56.67 13.01,56.67 12.7,56.98
N$173
  Bottom 1.27: 11.74,57.3 12.38,57.3
N$174
  Bottom 1.27: 5.71,48.09 6.03,48.09
N$175
  Bottom 0.406: 4.44,46.82 4.12,47.14 3.8,47.14 4.12,46.82
N$176
  Bottom 1.016: 4.44,51.59 4.44,50.32 4.12,50 2.85,50 2.85,50.32 3.8,51.27 3.8,50.63
N$177
  Bottom 1.27: 8.89,5.23 8.89,10.95
N$178
  Bottom 1.27: 10.16,5.23 10.16,9.36
N$179
  Bottom 1.27: 9.52,5.23 9.52,10.31
N$180
  Bottom 0.61: 6.98,0.47 12.7,0.47
N$181
  Bottom 1.27: 76.51,7.77 76.51,8.09
N$182
  Bottom 1.27: 79.05,21.11 77.78,21.11 77.78,24.6 79.37,24.6 79.37,21.42
N$183
  Bottom 1.27: 79.05,40.79 77.78,40.79 77.78,43.65 79.37,43.65 79.37,41.43
N$184
  Bottom 1.27: 12.38,89.05 12.38,87.47
N$185
  Bottom 1.27: 12.38,67.78 12.38,69.37
N$187
  Bottom 1.27: 10.79,84.29 7.93,84.29 7.93,82.39 | 7.93,81.43 7.93,82.39 | 7.93,82.39 9.52,83.97 9.52,83.02 8.89,82.39
N$188
  Bottom 1.016: 2.54,53.49 0.63,51.59 0.63,53.49 1.58,53.49 0.95,52.86
N$189
  Bottom 0.61: 3.17,32.22 5.08,32.22 6.03,33.17 6.03,33.49 | 6.03,33.49 6.03,33.81 | 6.03,33.81 US1.15 | 6.03,33.49 5.08,32.54 I2C.4 | 3.17,32.85 5.08,32.85 6.03,33.81
N$190
  Bottom 0.61: 2.85,32.85 2.85,32.22
N$191
  Bottom 0.406: 46.67,22.38 46.67,21.11 | 46.67,32.22 46.67,30.95 | 46.67,42.22 46.67,42.38 | 46.51,42.22 46.67,42.22 | 46.67,42.22 46.67,40.79
  Bottom 0.61: 3.17,37.3 4.44,37.3 4.76,37.62 4.76,37.94 | US1.10 13.01,45.24 13.11,45.34 US1.9 | 4.76,45.24 US1.16 4.76,47.46 | 4.76,45.24 4.76,38.57 | 4.76,38.57 4.76,37.94 | 4.76,37.94 4.44,37.62 I2C.2 | 4.76,47.46 12.38,47.46 12.38,47.14 US1.10 | US1.10 12.38,45.24 | C25.2 2.85,47.46 4.76,47.46 | US1.8 13.65,51.59 13.55,51.49 US1.7 | 4.76,45.24 4.76,45.87 3.8,46.82 2.54,46.82 | 3.17,37.94 4.12,37.94 4.76,38.57
  Bottom 0.813: 11.74,47.78 12.38,47.14 12.38,44.6 13.97,44.6
  Bottom 1.016: 59.05,30 59.05,32.85 58.1,33.81 48.26,33.81 46.67,32.22 45.08,33.81 31.11,33.81 30.16,32.85 30.16,29.68 | 59.05,68.1 59.05,70.95 58.1,71.91 47.94,71.91 46.67,70.64 45.4,71.91 31.11,71.91 30.16,70.95 30.16,67.46 | 59.05,78.26 59.05,80.8 58.1,81.75 47.94,81.75 46.67,80.48 45.4,81.75 31.11,81.75 30.16,80.8 30.16,77.3 | 59.05,57.94 59.05,61.11 58.1,62.06 47.94,62.06 46.67,60.8 45.4,62.06 31.11,62.06 30.16,61.11 30.16,57.3 | 59.05,39.52 59.05,42.7 58.1,43.65 48.26,43.65 46.67,42.06 46.51,42.22 45.08,43.65 31.11,43.65 30.16,42.7 30.16,40.79 | 30.16,39.52 30.16,40.79 | 59.05,19.84 59.05,23.01 58.1,23.96 48.26,23.96 46.67,22.38 45.08,23.96 31.11,23.96 30.16,23.01 30.16,19.84 | 45.08,39.2 46.67,40.79 48.26,39.2 | 48.26,29.36 46.67,30.95 45.08,29.36 | 45.08,19.52 46.67,21.11 48.26,19.52 | 31.43,19.84 29.84,21.42 | 31.43,29.68 29.84,31.27 | 30.16,40.79 31.74,39.2 | 57.78,39.52 59.37,41.11 | 57.78,29.68 59.37,31.27 | 57.78,19.84 59.37,21.42 | 57.78,57.94 59.37,59.52 | 57.78,67.78 59.37,69.37 | 57.78,77.62 59.37,79.21 | 31.43,77.3 29.84,78.89 | 31.43,67.46 29.84,69.05 | 31.43,57.62 29.84,59.21 | 47.94,67.78 46.67,69.05 45.4,67.78 | 45.4,77.62 46.67,78.89 47.94,77.62 | 45.4,57.94 46.67,59.21 48.26,57.62 | 47.94,9.36 46.98,8.41 | 46.35,8.41 45.4,9.36
  Bottom 1.27: 12V.2 71.11,92.86 72.7,91.28 | K7.10 72.7,54.13 71.43,52.86 69.53,52.86 69.53,43.97 71.43,43.97 72.38,43.02 | 16.5,42.7 17.77,43.97 19.68,43.97 19.68,52.86 17.77,52.86 16.5,54.13
  Bottom 1.422: 44.76,90.32 44.76,92.23 | 44.76,90.32 44.76,88.73 | 44.76,88.73 44.76,87.47 45.08,87.15 | 16.5,82.39 K4.10 K4.3 16.5,72.54 | 16.5,82.39 K2.3 K2.10 16.5,90.96 | 16.5,72.54 K6.10 K6.3 16.5,62.7 | 16.5,62.7 K8.10 K8.3 16.5,54.13 16.5,51.59 | 16.5,8.09 K16.3 15.55,7.14 15.55,43.02 13.97,44.6 13.65,44.92 US1.9 | 16.5,8.09 K16.10 16.5,14.76 | 16.5,14.76 K14.3 K14.10 K12.3 K12.10 K10.3 K10.10 16.5,42.7 16.5,50.95 | 53.02,29.68 42.22,29.68 42.22,25.87 41.27,24.92 38.73,24.92 37.78,25.87 37.78,27.46 C19.2 35.55,29.68 31.74,29.68 | 37.78,16.03 37.78,17.61 C22.2 35.55,19.84 32.06,19.84 | 37.78,16.03 38.73,15.08 41.27,15.08 42.22,16.03 42.22,19.52 42.54,19.84 53.02,19.84 | 53.02,39.52 42.54,39.52 42.22,39.2 42.22,35.71 41.27,34.76 38.73,34.76 37.78,35.71 37.78,37.3 C16.2 35.55,39.52 32.06,39.52 | 53.02,77.62 47.94,77.62 45.4,77.62 42.22,77.62 42.22,73.81 41.27,72.86 38.73,72.86 37.78,73.81 37.78,75.4 C7.2 32.06,77.3 | 53.02,67.78 47.94,67.78 45.4,67.78 42.22,67.78 42.22,63.97 41.27,63.02 38.73,63.02 37.78,63.97 37.78,65.56 C10.2 32.06,67.46 | 53.02,57.94 45.4,57.94 42.22,57.94 42.22,54.13 41.27,53.17 38.73,53.17 37.78,54.13 37.78,55.71 C13.2 32.06,57.62 | 26.35,87.47 C4.2 | 62.86,87.47 C1.2 | 33.33,87.47 38.41,87.47 | 32.38,87.47 33.33,87.47 | 32.38,87.47 26.35,87.47 | 50.8,87.47 45.72,87.47 | 45.72,87.47 43.81,87.47 | 38.41,87.47 43.81,87.47 | 56.83,87.47 50.8,87.47 | 56.83,87.47 57.78,87.47 | 57.78,87.47 62.86,87.47 | 50.8,87.47 C2.2 | 38.41,87.47 C3.2 | 72.7,7.46 K15.10 73.66,7.14 73.66,47.46 | 72.7,7.46 K15.3 72.7,14.76 | 72.7,14.76 K13.10 K13.3 72.7,24.6 | 72.7,24.6 K11.10 K11.3 K9.10 K9.3
  Bottom 1.422: 72.7,82.07 K3.3 K3.10 72.7,72.54 | 72.7,82.39 72.7,82.07 | 72.7,82.39 K1.10 K1.3 72.7,91.28 | 72.7,72.54 K5.3 K5.10 K7.3 K7.10 72.7,48.41 | 23.81,7.14 26.98,9.68 27.27,9.39 L24.1 | 23.81,19.84 26.98,19.84 | 26.98,19.84 30.16,19.84 31.43,19.84 32.06,19.84 | 23.81,19.84 23.81,7.14 | L21.4 27.02,19.8 26.98,19.84 | L21.5 32.02,19.8 32.06,19.84 | 23.81,29.68 26.98,29.68 | 26.98,29.68 30.16,29.68 31.43,29.68 31.74,29.68 | 23.81,29.68 23.81,19.84 | L18.4 27.02,29.64 26.98,29.68 | L18.5 32.02,29.4 31.74,29.68 | 26.98,39.52 23.81,39.52 23.81,39.2 | 26.98,39.52 30.16,39.52 32.06,39.52 | 23.81,39.2 23.81,29.68 | L15.5 32.02,39.48 32.06,39.52 | L15.4 27.02,39.48 26.98,39.52 | 53.02,19.84 C20.2 | 65.4,19.84 62.23,19.84 | 57.15,19.84 53.02,19.84 | 57.15,19.84 57.78,19.84 59.05,19.84 62.23,19.84 | L19.2 62.19,19.8 62.23,19.84 | 57.15,19.84 57.19,19.8 L19.1 53.34,13.17 C23.2 | 53.02,29.68 C17.2 | 57.15,29.68 53.02,29.68 | 57.15,29.68 57.78,29.68 62.23,29.68 | 65.4,29.68 62.23,29.68 | 65.4,29.68 65.4,19.84 | L16.2 62.19,29.64 62.23,29.68 | L16.1 57.19,29.64 57.15,29.68 | 53.02,39.52 C14.2 | 62.23,39.52 65.4,39.52 65.4,38.89 | 57.15,39.52 53.02,39.52 | 57.15,39.52 57.78,39.52 59.05,39.52 62.23,39.52 | 65.4,38.89 65.4,29.68 | L13.2 62.19,39.48 62.23,39.52 | L13.1 57.19,39.48 57.15,39.52 | 53.02,57.94 C11.2 | 57.46,57.94 53.02,57.94 | 57.46,57.94 57.78,57.94 59.05,57.94 62.23,57.94 | 62.23,57.94 65.4,57.94 65.4,58.25 | 53.02,77.62 C5.2 | 65.4,77.62 62.23,77.62 | 57.15,77.62 57.78,77.62 62.23,77.62 | 57.15,77.62 53.02,77.62 | 53.02,67.78 C8.2 | 65.4,67.78 62.23,67.78 | 57.46,67.78 57.78,67.78 62.23,67.78 | 57.46,67.78 53.02,67.78 | 65.4,77.62 65.4,67.78
  Bottom 1.422: 65.4,67.78 65.4,58.25 | L4.2 62.19,77.58 62.23,77.62 | L4.1 57.19,77.58 57.15,77.62 | L7.2 62.19,67.74 62.23,67.78 | L7.1 57.19,67.5 57.46,67.78 | 62.23,57.94 62.19,57.9 L10.2 62.19,53.53 64.77,50.95 64.77,50.96 X1.2 | L10.1 57.19,57.66 57.46,57.94 | 23.81,77.3 26.98,77.3 | 26.98,77.3 30.16,77.3 31.43,77.3 32.06,77.3 | 23.81,57.62 23.81,55.08 | 23.81,67.46 23.81,57.62 | 23.81,77.3 23.81,67.46 | L12.4 26.98,55.08 23.81,55.08 | L6.5 32.02,77.27 32.06,77.3 | L6.4 27.02,77.27 26.98,77.3 | 23.81,67.46 26.98,67.46 | 26.98,67.46 30.16,67.46 31.43,67.46 32.06,67.46 | L9.4 27.02,67.42 26.98,67.46 | L9.5 32.02,67.42 32.06,67.46 | 23.81,57.62 31.43,57.62 32.06,57.62 | 62.86,87.47 65.4,87.47 65.4,77.62 | 23.81,77.3 23.81,87.47 26.35,87.47 | L12.5 32.02,57.58 32.06,57.62 | 72.7,48.41 K9.3 | 72.7,48.41 75.24,48.41 | 75.24,48.41 C28.- | 72.7,91.28 70.16,93.81 64.77,93.81 | 64.77,93.81 62.86,91.91 58.41,91.91 | 58.41,91.91 58.1,91.91 56.83,90.64 | 56.83,90.64 56.83,88.73 | 56.83,88.73 56.83,87.47 | 56.83,88.42 57.78,87.47 | 56.83,88.73 56.83,88.42 | 56.83,88.42 55.56,87.15 | 16.5,90.96 16.5,91.28 19.04,93.81 23.81,93.81 | 23.81,93.81 24.12,93.81 26.03,91.91 30.79,91.91 | 30.79,91.91 31.11,91.91 32.38,90.64 | 32.38,90.64 32.38,88.42 | 32.38,88.42 32.38,87.47 | 32.38,88.42 33.33,87.47 | 32.38,88.42 31.74,87.78 | 32.38,90.64 33.65,91.91 33.97,91.91 | 33.97,91.91 43.18,91.91 | 43.18,91.91 46.67,91.91 | 55.56,91.91 46.67,91.91 | 58.41,91.91 55.56,91.91 | 55.56,91.91 56.83,90.64 | 30.79,91.91 33.97,91.91 | 23.81,93.81 64.77,93.81 | 44.76,88.42 45.72,87.47 | 44.76,88.73 44.76,88.42 | 44.76,88.42 43.81,87.47 | 46.67,91.91 46.35,91.91 44.76,90.32 | 43.18,91.91 44.76,90.32
  Bottom 1.422: 16.5,90.96 16.5,93.81 | 16.5,93.81 17.46,93.81 | 17.46,93.81 18.73,93.81 | 17.46,93.81 16.82,93.18 | 72.7,82.39 69.84,82.39 69.84,82.07 72.7,82.07 | 72.7,72.54 69.84,72.54 69.84,72.22 72.38,72.22 | 16.5,82.39 19.36,82.39 19.36,82.07 17.14,82.07 | 16.5,72.54 19.36,72.54 19.36,72.22 17.14,72.22 | 16.5,62.7 19.36,62.7 19.36,62.38 16.82,62.38 | 16.5,93.81 15.55,93.81 15.55,56.98 | 72.7,91.28 73.66,90.32 73.66,50 74.92,48.73 73.97,48.73 73.34,49.37 | 75.24,48.41 73.66,46.82 73.66,47.46 | 73.66,47.46 73.66,47.78 | 72.7,24.6 69.84,24.6 69.84,24.28 72.07,24.28 | 72.7,14.76 69.84,14.76 69.84,14.44 73.02,14.44 | 16.5,14.76 19.36,14.76 19.36,14.44 17.14,14.44 | K9.3 72.7,7.46 | 72.7,7.46 72.7,6.18 | 16.5,50.95 16.5,51.59 | X2.2 16.52,50.96 16.5,50.95 | US1.8 16.4,51.49 16.5,51.59 | 16.5,8.09 16.5,5.87 | 65.4,58.25 65.4,38.89 | 23.81,55.08 23.81,39.2 | C26.2 35.87,14.12 37.78,16.03 | L22.5 65.37,7.11 65.4,7.46 65.4,19.84 | 23.81,7.14 28.25,7.14 30.79,9.68 C26.2 | C26.2 37.78,11.58 37.78,13.49 38.73,14.44 41.27,14.44 42.22,13.49 42.22,9.36 45.4,9.36 47.94,9.36 58.73,9.36 60.96,7.14 65.4,7.14
N$192
  Bottom 0.61: 2.85,37.94 2.85,37.3
N$193
  Bottom 1.27: 78.73,27.77 76.51,27.77 76.19,28.09
N$195
  Bottom 0.305: 68.57,1.42 63.81,0.79 | 63.81,0.79 63.5,0.79 | 68.57,1.42 70.48,1.42 | 68.57,1.42 68.26,1.42 67.3,0.47 | 68.26,0.79 67.94,0.79 68.57,1.42 | 63.81,0.79 64.13,0.47 | 68.57,1.42 14.28,1.42 13.65,2.06
  Bottom 0.406: D1.C 76.08,85.77 75.88,85.56 | 75.88,78.58 76.19,78.58 76.08,78.46 D2.C | D3.C 76.08,68.21 75.88,68.41 | 75.88,58.57 76.19,58.57 76.08,58.46 D4.C
  Bottom 0.61: 46.35,96.67 45.72,96.67 45.4,96.36 | 51.43,96.67 50.16,96.67 | 50.16,96.67 50.48,96.67 | 51.43,96.67 52.07,96.67 52.07,96.36 51.11,96.36 | 51.43,96.67 50.48,96.67 | 50.8,96.04 45.08,96.04 | 51.43,96.67 50.8,96.04 | 51.43,96.67 46.35,96.67 | 46.35,96.67 46.03,96.36 | 51.43,96.04 52.38,96.04 | 51.43,96.04 51.11,96.04 50.48,96.67 | 50.8,96.04 51.43,96.04 | 50.16,96.67 50.48,96.36 50.8,96.04 | 13.33,36.35 13.01,36.66 | 62.86,0.79 63.18,0.47 64.13,0.47 67.3,0.47 68.57,0.47 68.89,0.79
  Bottom 1.016: 46.03,96.36 50.48,96.36
  Bottom 1.27: 79.05,27.77 79.37,27.77 79.37,26.82 78.42,26.82 | 76.19,6.5 79.37,6.5 79.37,8.09 77.46,8.09 75.88,9.68 | 13.33,89.69 K2.12 11.43,86.83 12.06,86.83 | 13.33,89.69 13.33,79.84 | 13.33,79.84 K4.12 | 13.33,70 K6.12 11.43,67.14 13.01,67.14 | 13.33,79.84 13.33,70 | K8.12 13.33,60.16 13.33,70 | 13.33,1.1 13.33,12.22 | 13.33,12.22 13.33,13.81 | 13.33,13.81 13.33,20.47 | 13.33,20.47 13.33,22.06 | 13.33,22.06 13.33,23.65 | 13.33,23.65 13.33,31.9 | 13.33,31.9 13.33,33.49 | 13.33,33.49 13.33,36.35 13.33,39.2 | 75.88,36.66 K9.12 78.73,36.66 79.05,36.98 D5.C 76.72,37.5 75.88,36.66 | 75.88,7.46 75.88,9.68 | 75.88,9.68 75.88,16.98 | 75.88,7.46 75.88,7.14 77.46,7.14 | 75.88,16.98 75.88,18.57 | 75.88,18.57 75.88,26.82 | 75.88,26.82 75.88,36.66 | 75.88,16.98 K13.12 78.42,16.98 | 75.88,26.82 K11.12 78.42,26.82 | D7.C 79.05,17.3 78.73,16.98 78.42,16.98 | D8.C 79.05,7.77 78.42,7.14 77.46,7.14 | 77.46,7.14 K15.12 | D6.C 79.05,27.14 78.73,26.82 78.42,26.82 | 75.88,60.48 75.88,60.16 | 75.88,60.48 75.88,64.92 | 75.88,64.92 75.88,68.41 75.88,74.77 | 75.88,74.77 75.88,78.58 75.88,84.61 | 73.66,93.5 12V.1 | 73.66,93.5 75.88,91.28 75.88,85.56 75.88,84.61 | 75.88,36.66 75.88,44.92 | 75.88,44.92 75.88,45.87 77.15,45.87 78.1,46.82 C28.+ 78.1,50 77.15,50.95 76.51,50.95 | 76.51,50.95 75.88,50.95 75.88,51.59 | 73.66,93.5 73.66,96.04 73.34,96.36 52.07,96.36 | 45.4,96.36 14.28,96.36 | 14.28,96.36 13.33,95.4 13.33,89.69 | 75.88,6.18 75.88,7.46 | 75.88,51.59 75.88,55.08 | 75.88,55.08 75.88,58.57 75.88,60.48 | 76.51,50.95 75.88,51.59 | 76.51,50.95 80,50.95 80,45.55 76.51,45.55 75.88,44.92 | 12.06,86.83 12.7,86.83 | 12.06,86.83 7.62,86.83 7.62,96.36 14.28,96.36
  Bottom 1.27: 75.88,18.57 76.51,17.93 79.37,17.93 79.37,16.98 78.42,16.98 | 13.33,12.22 K16.12 13.01,10.63 | 13.33,22.06 11.74,22.06 | 13.33,31.9 11.74,31.9 | 11.74,31.9 K12.12 13.01,30.31 13.01,31.27 12.7,31.58 | K10.12 12.38,41.74 13.33,40.79 13.33,39.2 | 68.26,0.79 62.86,0.79 | 13.33,39.2 11.43,41.11 | 11.43,41.11 11.43,41.43 | 11.43,41.11 11.43,40.48 12.38,40.48 | 13.33,33.49 11.74,31.9 | 11.74,22.06 K14.12 | 13.33,20.47 11.74,22.06 | 11.74,22.06 13.33,23.65 | 13.33,13.81 12.06,12.54 | 75.88,55.08 K7.12 | 75.88,64.92 K5.12 | 75.88,74.77 K3.12 | 75.88,84.61 K1.12
  Bottom 1.422: 13.33,1.1 13.33,0.79 62.86,0.79 | 68.89,0.79 70.48,0.79 75.88,6.18
N$196
  Bottom 0.406: 75.56,90.96 73.02,93.5 73.02,95.4 72.38,96.04
N$197
  Bottom 0.406: 73.02,95.72 73.34,95.72
N$198
  Bottom 0.406: 73.66,96.67 74.29,96.04 74.29,93.18
(copper drawn outside any net)
  shapes: Bottom area x36, Bottom circle x12

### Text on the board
Bottom: Bandpass Filters 0-30MHz | Michal Slomkowski | 2009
